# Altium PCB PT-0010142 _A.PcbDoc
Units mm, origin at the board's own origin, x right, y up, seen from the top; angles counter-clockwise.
Board outline 29.4 x 66.3 mm, 3 copper layers (Top Layer, MidLayer1, Bottom Layer), stack 1.608 mm thick; 32 components, 11 nets, 109 pads, 881 vias.
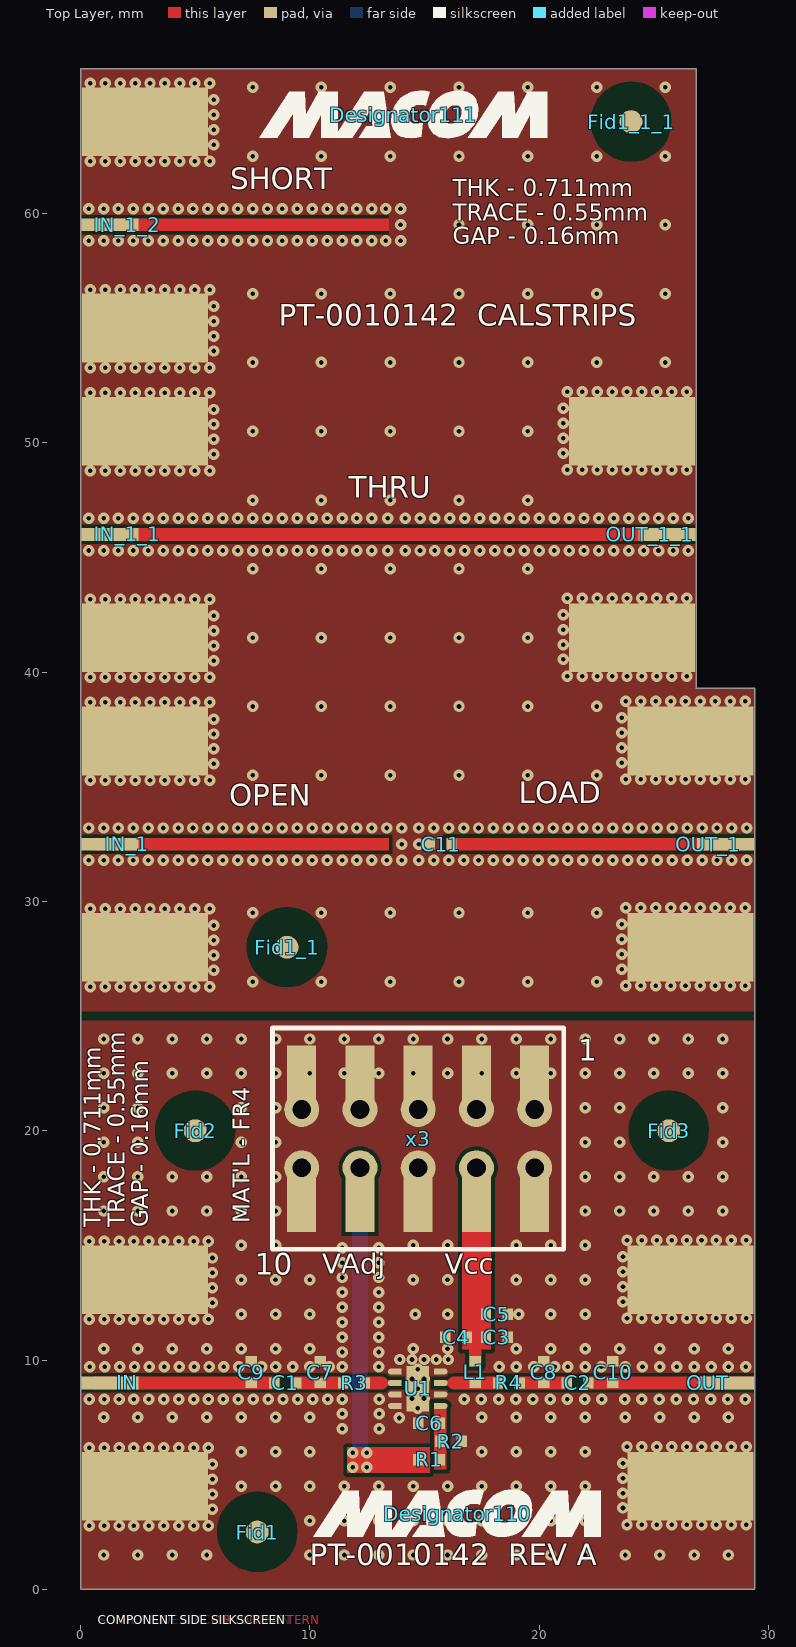
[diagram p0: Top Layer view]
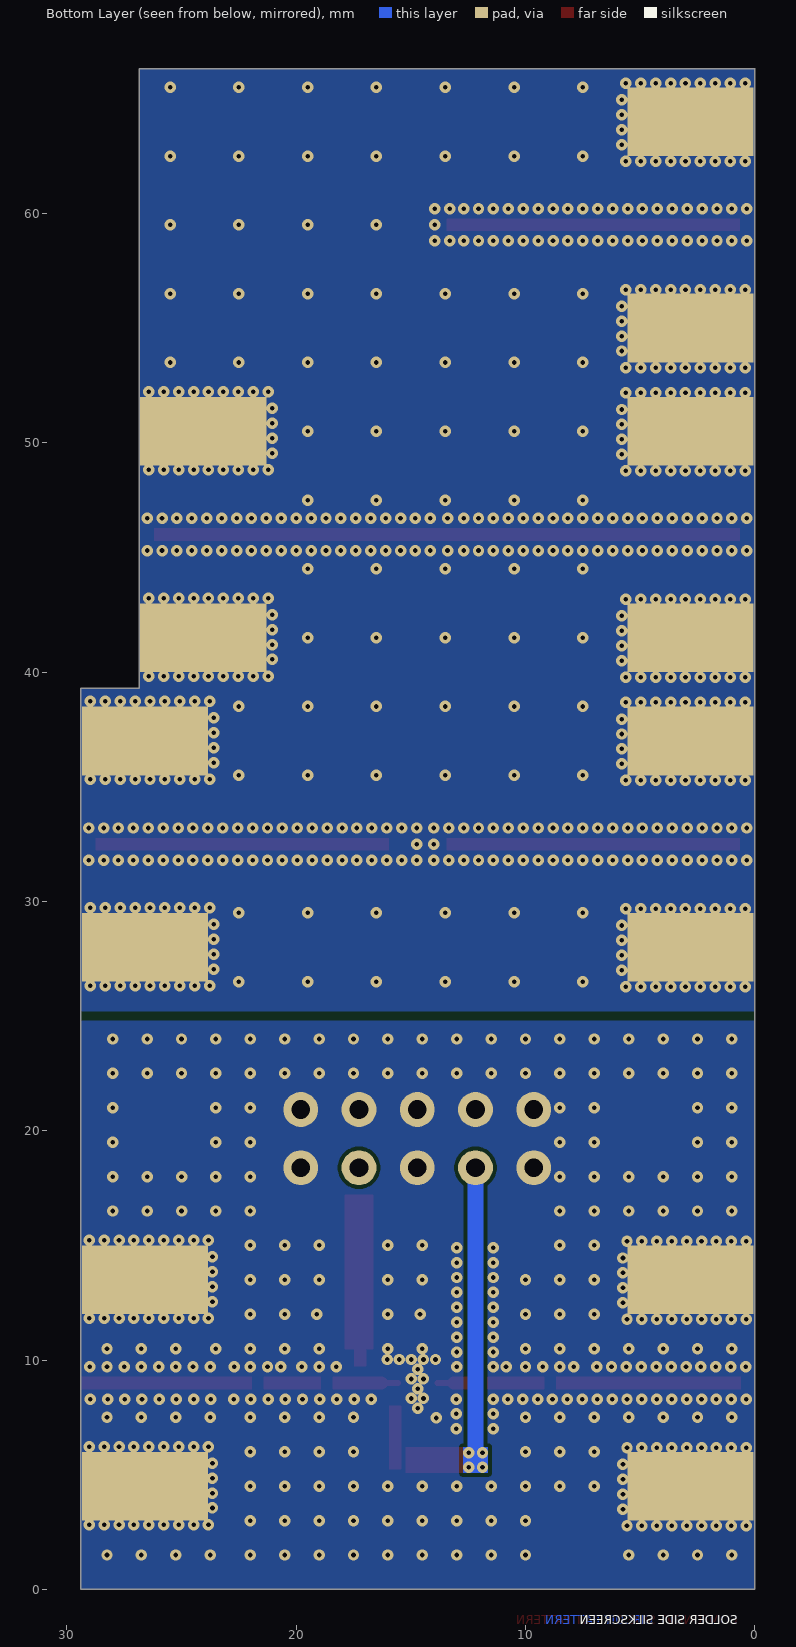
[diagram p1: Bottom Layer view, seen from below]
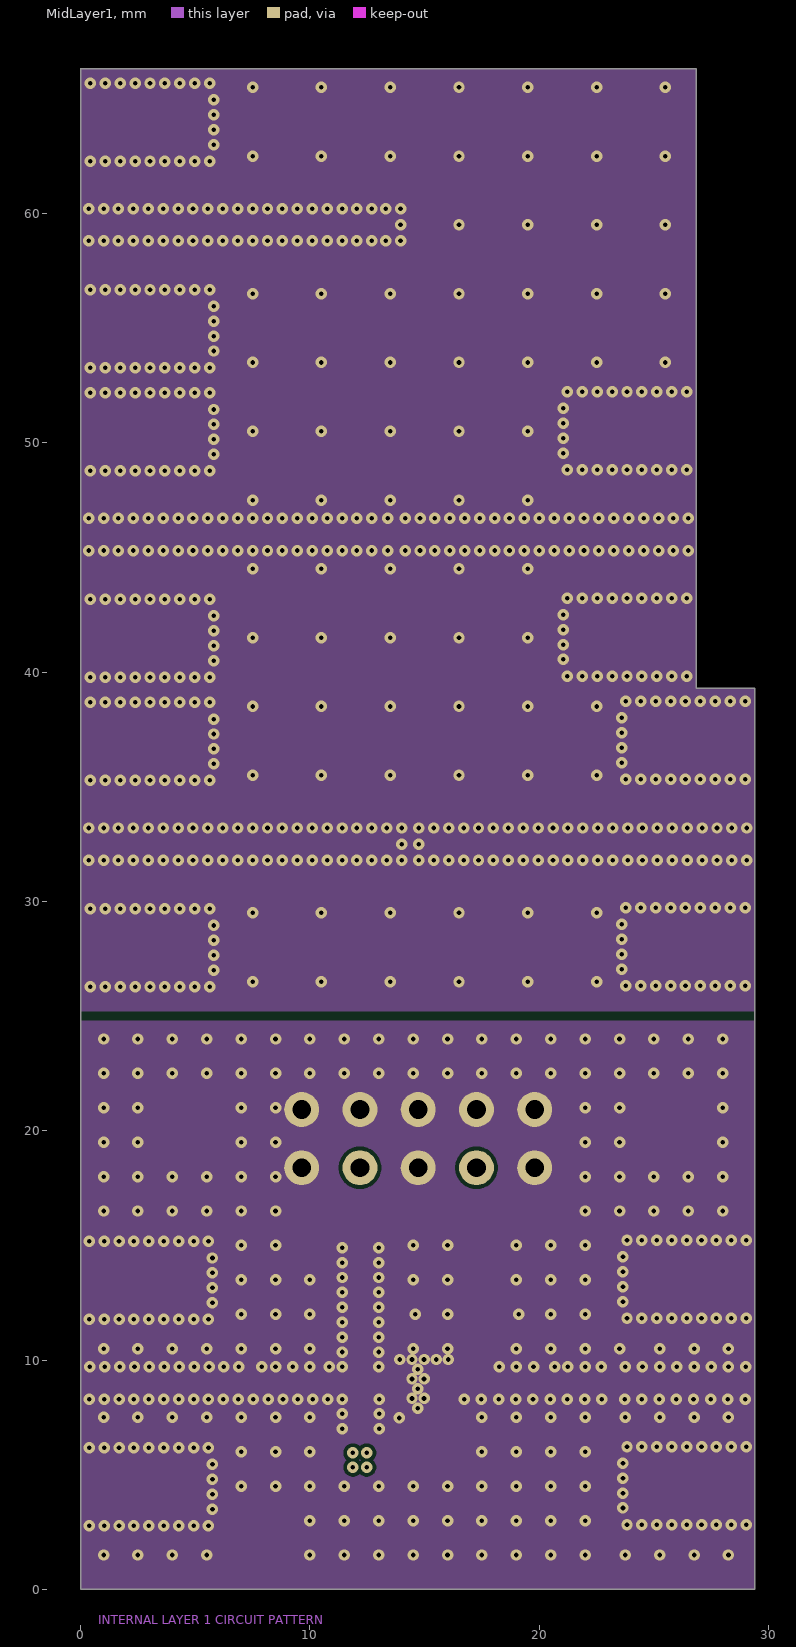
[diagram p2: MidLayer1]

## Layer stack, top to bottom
Top Solder: solder mask 0.0102, Solder Resist, Dk 3.5
Top Layer: signal copper 0.0356
Dielectric1: core 0.711, FR-4, Dk 4.8
MidLayer1: signal copper 0.0356
Dielectric2: prepreg 0.79, FR-4, Dk 4.8
Bottom Layer: signal copper 0.0356
Bottom Solder: solder mask 0.0102, Solder Resist, Dk 3.5

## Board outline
0,0 0,25 0,66.3 26.85,66.3 26.85,39.3 29.4,39.3 29.4,25 29.4,0

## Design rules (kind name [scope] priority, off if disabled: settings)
Clearance [All] p1: gap=0.16
ComponentClearance [All] p1: gap=0.15 collisioncheckmode=3 verticalgap=0.254 showdistances=FALSE
HoleSize [All] p1: absolutevalues=TRUE maxlimit=2.54 minlimit=0.02 maxpercent=80.000 minpercent=20.000
HoleToHoleClearance [All] p1: gap=0.15 allowstackedmicrovias=TRUE
MinimumSolderMaskSliver [All] p1: minsoldermaskwidth=0.149
PolygonConnect [All] p1: connectstyle=Direct reliefconductorwidth=0.254 reliefentries=4 polygonreliefangle="90 Angle" airgapwidth=0.254
RoomDefinition U_Individual [InComponentClass('U_Individual')] p1: confinementstyle=ConfineIn formatcopy=TRUE lockcomponents=FALSE outline -24.6,0 80.125,0 80.125,37 -24.6,37
RoomDefinition Sheet1 [InComponentClass('Sheet1')] p2: confinementstyle=ConfineIn formatcopy=TRUE lockcomponents=FALSE outline -24.875,-0.275 80.025,-0.275 80.025,37.2 -24.875,37.2
RoutingVias [All] p1: holewidth=0.25 width=0.5 viastyle="Through Hole" minholewidth=0.2 minwidth=0.6 maxholewidth=1 maxwidth=1.4
SilkToSilkClearance [All] p1: silktosilkclearance=0.2
SilkToSolderMaskClearance SilkscreenOverComponentPads [IsPad] p1: minsilkscreentomaskgap=0.1 clearancetoexposedcopper=TRUE
SolderMaskExpansion [All] p1: expansion=0.075
Width [All] p1: maxlimit=1.27 minlimit=0.2 preferedwidth=0.2
24 further rules are at their usual default settings.

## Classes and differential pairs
component class Sheet1: X3
component class U_Individual: R4

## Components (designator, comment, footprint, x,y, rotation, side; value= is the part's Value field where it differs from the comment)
C1 "#NAME?" 0402 8.925,9 r180 top
C2 "#NAME?" 0402 21.675,9 r180 top
C3 "#NAME?" 0402 18.15,11 r180 top
C4 "#NAME?" 0402 16.375,11 r180 top
C5 "#NAME?" 0402 18.15,12 r180 top
C6 "#NAME?" 0402 15.2,7.25 r0 top
C7 "#NAME?" 0402 10.45,9.475 r270 top
C8 "#NAME?" 0402 20.2,9.475 r270 top
C9 "#NAME?" 0402 7.45,9.475 r270 top
C10 "#NAME?" 0402 23.2,9.475 r270 top
C11 "#NAME?" 0402 15.7,32.5 r180 top (schematic designator C3)
Designator110 "Comment" LOGO-MACOM 16.425,3.3 r0 top
Designator111 "Comment" LOGO-MACOM 14.075,64.3 r0 top
Fid1 "Comment" Fiducial_1 7.7,2.5 r270 top
Fid1_1 "Comment" Fiducial_1 9,28 r270 top
Fid1_1_1 "Comment" Fiducial_1 24,64 r270 top
Fid2 "Comment" Fiducial_1 5,20 r270 top
Fid3 "Comment" Fiducial_1 25.65,20 r270 top
IN "Comment" "SMA_ Emerson_142-0701-851" 0,9 r0 top
IN_1 "Comment" "SMA_ Emerson_142-0701-851" 0,32.5 r0 top
IN_1_1 "Comment" "SMA_ Emerson_142-0701-851" 0,46 r0 top
IN_1_2 "Comment" "SMA_ Emerson_142-0701-851" 0,59.5 r0 top
L1 "#NAME?" 0402 17.2,9.475 r270 top
OUT "Comment" "SMA_ Emerson_142-0701-851" 29.4,9 r180 top
OUT_1 "Comment" "SMA_ Emerson_142-0701-851" 29.4,32.5 r180 top
OUT_1_1 "Comment" "SMA_ Emerson_142-0701-851" 26.85,46 r180 top
R1 "#NAME?" 0402 15.2,5.65 r0 top
R2 "#NAME?" 0402 16.15,6.45 r0 top
R3 "#NAME?" 0402 11.925,9 r180 top
R4 "#NAME?" 0402 18.675,9 r180 top
U1 "Comment" PDFN-8_2mm_Standard 14.7,8.75 r270 top
x3 "2X5_DUAL" 2X5_DUAL 19.8,20.925 r0 top locked (schematic designator X3)

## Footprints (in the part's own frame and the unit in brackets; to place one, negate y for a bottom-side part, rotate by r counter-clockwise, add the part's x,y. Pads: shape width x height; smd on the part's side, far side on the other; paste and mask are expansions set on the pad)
2X5_DUAL [mil]
  round 60 hole 32: 1(0,0) 2(0,-100) 3(-100,0) 4(-100,-100) 5(-200,0) 6(-200,-100) 7(-300,0) 8(-300,-100) 9(-400,0) 10(-400,-100)
  rect 50x110 smd: 1(0,55) 2(0,-155) 3(-100,55) 4(-100,-155) 5(-200,55) 6(-200,-155) 7(-300,55) 8(-300,-155) 9(-400,55) 10(-400,-155)
  silkscreen extent -450,-240 50,140, body extent -451,-150 49,50, height 205
0402 [mm]
  rect 0.45x0.5 smd mask+0.075: 1(-0.475,0) 2(0.475,0)
  body extent -0.5,-0.3 0.5,0.3, height 0.19
Fiducial_1 [mm] "Standard_1mm_Copper_3mm_Mask"
  round 1 smd paste-1 mask+1: 0(0,0)
  Top Layer pour cut-out: -1.75,-0.15 -1.725,-0.3 -1.675,-0.5 -1.6,-0.7 -1.507,-0.892 -1.35,-1.125 -1.175,-1.3 -1.025,-1.425 -0.875,-1.525 -0.65,-1.625 -0.35,-1.725 -0.125,-1.75 0.125,-1.75 0.45,-1.7 0.75,-1.575 1.05,-1.4 1.3,-1.175 1.45,-0.975 1.575,-0.775 1.65,-0.55 1.725,-0.275 1.75,0 1.725,0.275 1.674,0.532 1.55,0.8 1.425,1 1.25,1.225 1.025,1.425 0.725,1.6 0.5,1.675 0.25,1.725 -0.05,1.75 -0.325,1.725 -0.6,1.65 -0.875,1.525 -1.05,1.4 -1.225,1.25 -1.35,1.1 -1.5,0.9 -1.597,0.732 -1.675,0.525 -1.725,0.325 -1.75,0.15
LOGO-MACOM [mm]
  silkscreen extent -6.29,-1.01 6.27,1.05
PDFN-8_2mm_Standard [mm]
  oval 0.25x0.6 smd mask+0.05: 1(-0.75,-1) 2(-0.25,-1) 3(0.25,-1) 4(0.75,-1) 5(0.75,1) 6(0.25,1) 7(-0.25,1) 8(-0.75,1)
  rect 0.25x0.2 smd mask+0.05: 1(-0.75,-0.8) 2(-0.25,-0.8) 3(0.25,-0.8) 4(0.75,-0.8) 5(0.75,0.8) 6(0.25,0.8) 7(-0.25,0.8) 8(-0.75,0.8)
  rect 2x1 smd paste-0.1 mask-0.075: 9(0,0)
  body extent -1,-1 1,1, height 1
"SMA_ Emerson_142-0701-851" [mm]
  rect 2.5x0.55 smd mask+0.075: 1(1.275,0)
  rect 5.5x3 smd mask+0.075: 2(2.8,-4.5) 2(2.8,4.5)
  rect 5.5x3 smd far side mask+0.075: 2(2.8,-4.5) 2(2.8,4.5)
  body extent -9.08,-4.76 4.75,4.76, height 3.96

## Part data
C1 C2 C3 C4 C5 C6 C7 C8 C9 C10 C11 L1 R1 R2 R3 R4: library part C0402, "Capacitor"

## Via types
v1: diameter 0.5, hole 0.2, Top Layer to Bottom Layer, tented both sides, 881 vias

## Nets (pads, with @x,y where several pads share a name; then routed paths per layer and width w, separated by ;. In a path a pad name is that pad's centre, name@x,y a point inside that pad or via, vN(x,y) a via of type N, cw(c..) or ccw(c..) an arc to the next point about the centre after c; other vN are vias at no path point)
1: R3.1 U1.2 | length 1.4
  Top Layer w0.25: 13.125,9 13.7,9 U1.2@13.85,9
  Top Layer w0.55: R3.1@12.45,9 13.125,9
2: C1.1 C7.2 R3.2
3: C1.2 C9.2 IN.1
4: L1.2 R4.2 U1.7 | length 2.4
  Top Layer w0.25: U1.7@15.55,9 15.7,9 16.275,9
  Top Layer w0.55: 16.275,9 17.95,9
5: C2.2 C8.2 R4.1
6: C2.1 C10.2 OUT.1
7: C6.2 R1.2 R2.1 U1.5
GND: C3.1 C4.2 C5.1 C6.1 C7.1 C8.1 C9.1 C10.1 IN.2 OUT.2 R2.2 U1.1 U1.3 U1.4 U1.6 U1.8 U1.9 x3.1 x3.2 x3.3 x3.5 x3.6 x3.7 x3.9 x3.10
  other v1: 1,1.5 2.5,1.5 4,1.5 5.5,1.5 10,1.5 11.5,1.5 13,1.5 14.5,1.5 16,1.5 17.5,1.5 19,1.5 20.5,1.5 22,1.5 23.75,1.5 25.25,1.5 26.75,1.5 28.25,1.5 0.375,2.775 1.025,2.775 1.675,2.775 2.325,2.775 2.975,2.775 3.625,2.775 4.275,2.775 4.925,2.775 5.575,2.775 23.825,2.825 24.475,2.825 25.125,2.825 25.775,2.825 26.425,2.825 27.075,2.825 27.725,2.825 28.375,2.825 29.025,2.825 10,3 11.5,3 13,3 14.5,3 16,3 17.5,3 19,3 20.5,3 22,3 5.75,3.5 23.65,3.55 5.75,4.15 23.65,4.2 7,4.5 8.5,4.5 10,4.5 11.5,4.5 13,4.5 14.5,4.5 16,4.5 17.5,4.5 19,4.5 20.5,4.5 22,4.5 5.75,4.8 23.65,4.85 5.75,5.45 23.65,5.5 7,6 8.5,6 10,6 17.5,6 19,6 20.5,6 22,6 0.375,6.175 1.025,6.175 1.675,6.175 2.325,6.175 2.975,6.175 3.625,6.175 4.275,6.175 4.925,6.175 5.575,6.175 23.825,6.225 24.475,6.225 25.125,6.225 25.775,6.225 26.425,6.225 27.075,6.225 27.725,6.225 28.375,6.225 29.025,6.225 11.4,7 13.025,7 13.9,7.475 1,7.5 2.5,7.5 4,7.5 5.5,7.5 7,7.5 8.5,7.5 10,7.5 17.5,7.5 19,7.5 20.5,7.5 22,7.5 23.75,7.5 25.25,7.5 26.75,7.5 28.25,7.5 11.4,7.65 13.025,7.65 14.7,7.9 0.375,8.3 1.025,8.3 1.675,8.3 2.325,8.3 2.975,8.3 3.625,8.3 4.275,8.3 4.925,8.3 5.575,8.3 6.225,8.3 6.875,8.3 7.525,8.3 8.175,8.3 8.825,8.3 9.475,8.3 10.125,8.3 10.775,8.3 11.4,8.3 13.025,8.3 16.725,8.3 17.475,8.3 18.225,8.3 18.975,8.3 19.725,8.3 20.475,8.3 21.225,8.3 21.975,8.3 22.725,8.3 23.725,8.3 24.475,8.3 25.225,8.3 25.975,8.3 26.725,8.3 27.475,8.3 28.225,8.3 28.975,8.3 14.45,8.325 14.975,8.325 14.7,8.75 14.45,9.175 14.975,9.175 14.7,9.6 0.4,9.7 1.05,9.7 1.7,9.7 2.35,9.7 3,9.7 3.65,9.7 4.3,9.7 4.95,9.7 5.6,9.7 6.25,9.7 6.9,9.7 7.9,9.7 8.5,9.7 9.25,9.7 10,9.7 10.85,9.7 11.4,9.7 13,9.7 18.25,9.7 19,9.7 19.75,9.7 20.675,9.7 21.25,9.7 22,9.7 22.7,9.7 23.75,9.7 24.5,9.7 25.25,9.7 26,9.7 26.75,9.7 27.5,9.7 28.25,9.7 29,9.7 13.925,10.025 14.45,10.025 14.975,10.025 15.5,10.025 16.025,10.025 11.4,10.35 13,10.35 1,10.5 2.5,10.5 4,10.5 5.5,10.5 7,10.5 8.5,10.5 10,10.5 14.5,10.5 16,10.5 19,10.5 20.5,10.5 22,10.5 23.5,10.5 25.25,10.5 26.75,10.5 28.25,10.5 11.4,11 13,11 11.4,11.65 13,11.65 0.375,11.775 1.025,11.775 1.675,11.775 2.325,11.775 2.975,11.775 3.625,11.775 4.275,11.775 4.925,11.775 5.575,11.775 23.825,11.825 24.475,11.825 25.125,11.825 25.775,11.825 26.425,11.825 27.075,11.825 27.725,11.825 28.375,11.825 29.025,11.825 7,12 8.5,12 10,12 14.6,12 16,12 19.1,12 20.5,12 22,12 11.4,12.3 13,12.3 5.75,12.5 23.65,12.55 11.4,12.95 13,12.95 5.75,13.15 23.65,13.2 7,13.5 8.5,13.5 10,13.5 14.5,13.5 16,13.5 19,13.5 20.5,13.5 22,13.5 11.4,13.6 13,13.6 5.75,13.8 23.65,13.85 11.4,14.25 13,14.25 5.75,14.45 23.65,14.5 11.4,14.9 13,14.9 7,15 8.5,15 14.5,15 16,15 19,15 20.5,15 22,15 0.375,15.175 1.025,15.175 1.675,15.175 2.325,15.175 2.975,15.175 3.625,15.175 4.275,15.175 4.925,15.175 5.575,15.175 23.825,15.225 24.475,15.225 25.125,15.225 25.775,15.225 26.425,15.225 27.075,15.225 27.725,15.225 28.375,15.225 29.025,15.225 1,16.5 2.5,16.5 4,16.5 5.5,16.5 7,16.5 8.5,16.5 22,16.5 23.5,16.5 25,16.5 26.5,16.5 28,16.5 1,18 2.5,18 4,18 5.5,18 7,18 8.5,18 22,18 23.5,18 25,18 26.5,18 28,18 1,19.5 2.5,19.5 7,19.5 8.5,19.5 22,19.5 23.5,19.5 28,19.5 1,21 2.5,21 7,21 8.5,21 22,21 23.5,21 28,21 1,22.5 2.5,22.5 4,22.5 5.5,22.5 7,22.5 8.5,22.5 10,22.5 11.5,22.5 13,22.5 14.5,22.5 16,22.5 17.5,22.5 19,22.5 20.5,22.5 22,22.5 23.5,22.5 25,22.5 26.5,22.5 28,22.5 1,24 2.5,24 4,24 5.5,24 7,24 8.5,24 10,24 11.5,24 13,24 14.5,24 16,24 17.5,24 19,24 20.5,24 22,24 23.5,24 25,24 26.5,24 28,24
GND2: C11.2 IN_1.2 IN_1_1.2 IN_1_2.1 IN_1_2.2 OUT_1.2 OUT_1_1.2
  other v1: 0.425,26.275 1.075,26.275 1.725,26.275 2.375,26.275 3.025,26.275 3.675,26.275 4.325,26.275 4.975,26.275 5.625,26.275 23.775,26.325 24.425,26.325 25.075,26.325 25.725,26.325 26.375,26.325 27.025,26.325 27.675,26.325 28.325,26.325 28.975,26.325 7.5,26.5 10.5,26.5 13.5,26.5 16.5,26.5 19.5,26.5 22.5,26.5 5.8,27 23.6,27.05 5.8,27.65 23.6,27.7 5.8,28.3 23.6,28.35 5.8,28.95 23.6,29 7.5,29.5 10.5,29.5 13.5,29.5 16.5,29.5 19.5,29.5 22.5,29.5 0.425,29.675 1.075,29.675 1.725,29.675 2.375,29.675 3.025,29.675 3.675,29.675 4.325,29.675 4.975,29.675 5.625,29.675 23.775,29.725 24.425,29.725 25.075,29.725 25.725,29.725 26.375,29.725 27.025,29.725 27.675,29.725 28.325,29.725 28.975,29.725 0.35,31.8 1,31.8 1.65,31.8 2.3,31.8 2.95,31.8 3.6,31.8 4.25,31.8 4.9,31.8 5.55,31.8 6.2,31.8 6.85,31.8 7.5,31.8 8.15,31.8 8.8,31.8 9.45,31.8 10.1,31.8 10.75,31.8 11.4,31.8 12.05,31.8 12.7,31.8 13.35,31.8 14,31.8 14.75,31.8 15.4,31.8 16.05,31.8 16.7,31.8 17.35,31.8 18,31.8 18.65,31.8 19.3,31.8 19.95,31.8 20.6,31.8 21.25,31.8 21.9,31.8 22.55,31.8 23.2,31.8 23.85,31.8 24.5,31.8 25.15,31.8 25.8,31.8 26.45,31.8 27.1,31.8 27.75,31.8 28.4,31.8 29.05,31.8 14,32.5 14.75,32.5 0.35,33.2 1,33.2 1.65,33.2 2.3,33.2 2.95,33.2 3.6,33.2 4.25,33.2 4.9,33.2 5.55,33.2 6.2,33.2 6.85,33.2 7.5,33.2 8.15,33.2 8.8,33.2 9.45,33.2 10.1,33.2 10.75,33.2 11.4,33.2 12.05,33.2 12.7,33.2 13.35,33.2 14,33.2 14.75,33.2 15.4,33.2 16.05,33.2 16.7,33.2 17.35,33.2 18,33.2 18.65,33.2 19.3,33.2 19.95,33.2 20.6,33.2 21.25,33.2 21.9,33.2 22.55,33.2 23.2,33.2 23.85,33.2 24.5,33.2 25.15,33.2 25.8,33.2 26.45,33.2 27.1,33.2 27.75,33.2 28.4,33.2 29.05,33.2 0.425,35.275 1.075,35.275 1.725,35.275 2.375,35.275 3.025,35.275 3.675,35.275 4.325,35.275 4.975,35.275 5.625,35.275 23.775,35.325 24.425,35.325 25.075,35.325 25.725,35.325 26.375,35.325 27.025,35.325 27.675,35.325 28.325,35.325 28.975,35.325 7.5,35.5 10.5,35.5 13.5,35.5 16.5,35.5 19.5,35.5 22.5,35.5 5.8,36 23.6,36.05 5.8,36.65 23.6,36.7 5.8,37.3 23.6,37.35 5.8,37.95 23.6,38 7.5,38.5 10.5,38.5 13.5,38.5 16.5,38.5 19.5,38.5 22.5,38.5 0.425,38.675 1.075,38.675 1.725,38.675 2.375,38.675 3.025,38.675 3.675,38.675 4.325,38.675 4.975,38.675 5.625,38.675 23.775,38.725 24.425,38.725 25.075,38.725 25.725,38.725 26.375,38.725 27.025,38.725 27.675,38.725 28.325,38.725 28.975,38.725 0.425,39.775 1.075,39.775 1.725,39.775 2.375,39.775 3.025,39.775 3.675,39.775 4.325,39.775 4.975,39.775 5.625,39.775 21.225,39.825 21.875,39.825 22.525,39.825 23.175,39.825 23.825,39.825 24.475,39.825 25.125,39.825 25.775,39.825 26.425,39.825 5.8,40.5 21.05,40.55 5.8,41.15 21.05,41.2 7.5,41.5 10.5,41.5 13.5,41.5 16.5,41.5 19.5,41.5 5.8,41.8 21.05,41.85 5.8,42.45 21.05,42.5 0.425,43.175 1.075,43.175 1.725,43.175 2.375,43.175 3.025,43.175 3.675,43.175 4.325,43.175 4.975,43.175 5.625,43.175 21.225,43.225 21.875,43.225 22.525,43.225 23.175,43.225 23.825,43.225 24.475,43.225 25.125,43.225 25.775,43.225 26.425,43.225 7.5,44.5 10.5,44.5 13.5,44.5 16.5,44.5 19.5,44.5 0.35,45.3 1,45.3 1.65,45.3 2.3,45.3 2.95,45.3 3.6,45.3 4.25,45.3 4.9,45.3 5.55,45.3 6.2,45.3 6.85,45.3 7.5,45.3 8.15,45.3 8.8,45.3 9.45,45.3 10.1,45.3 10.75,45.3 11.4,45.3 12.05,45.3 12.7,45.3 13.4,45.3 14.15,45.3 14.8,45.3 15.45,45.3 16.1,45.3 16.75,45.3 17.4,45.3 18.05,45.3 18.7,45.3 19.35,45.3 20,45.3 20.65,45.3 21.3,45.3 21.95,45.3 22.6,45.3 23.25,45.3 23.9,45.3 24.55,45.3 25.2,45.3 25.85,45.3 26.5,45.3 0.35,46.7 1,46.7 1.65,46.7 2.3,46.7 2.95,46.7 3.6,46.7 4.25,46.7 4.9,46.7 5.55,46.7 6.2,46.7 6.85,46.7 7.5,46.7 8.15,46.7 8.8,46.7 9.45,46.7 10.1,46.7 10.75,46.7 11.4,46.7 12.05,46.7 12.7,46.7 13.4,46.7 14.15,46.7 14.8,46.7 15.45,46.7 16.1,46.7 16.75,46.7 17.4,46.7 18.05,46.7 18.7,46.7 19.35,46.7 20,46.7 20.65,46.7 21.3,46.7 21.95,46.7 22.6,46.7 23.25,46.7 23.9,46.7 24.55,46.7 25.2,46.7 25.85,46.7 26.5,46.7 7.5,47.5 10.5,47.5 13.5,47.5 16.5,47.5 19.5,47.5 0.425,48.775 1.075,48.775 1.725,48.775 2.375,48.775 3.025,48.775 3.675,48.775 4.325,48.775 4.975,48.775 5.625,48.775 21.225,48.825 21.875,48.825 22.525,48.825 23.175,48.825 23.825,48.825 24.475,48.825 25.125,48.825 25.775,48.825 26.425,48.825 5.8,49.5 21.05,49.55 5.8,50.15 21.05,50.2 7.5,50.5 10.5,50.5 13.5,50.5 16.5,50.5 19.5,50.5 5.8,50.8 21.05,50.85 5.8,51.45 21.05,51.5 0.425,52.175 1.075,52.175 1.725,52.175 2.375,52.175 3.025,52.175 3.675,52.175 4.325,52.175 4.975,52.175 5.625,52.175 21.225,52.225 21.875,52.225 22.525,52.225 23.175,52.225 23.825,52.225 24.475,52.225 25.125,52.225 25.775,52.225 26.425,52.225 0.425,53.275 1.075,53.275 1.725,53.275 2.375,53.275 3.025,53.275 3.675,53.275 4.325,53.275 4.975,53.275 5.625,53.275 7.5,53.5 10.5,53.5 13.5,53.5 16.5,53.5 19.5,53.5 22.5,53.5 25.5,53.5 5.8,54 5.8,54.65 5.8,55.3 5.8,55.95 7.5,56.5 10.5,56.5 13.5,56.5 16.5,56.5 19.5,56.5 22.5,56.5 25.5,56.5 0.425,56.675 1.075,56.675 1.725,56.675 2.375,56.675 3.025,56.675 3.675,56.675 4.325,56.675 4.975,56.675 5.625,56.675 0.35,58.8 1,58.8 1.65,58.8 2.3,58.8 2.95,58.8 3.6,58.8 4.25,58.8 4.9,58.8 5.55,58.8 6.2,58.8 6.85,58.8 7.5,58.8 8.15,58.8 8.8,58.8 9.45,58.8 10.1,58.8 10.75,58.8 11.4,58.8 12.05,58.8 12.7,58.8 13.3,58.8 13.95,58.8 13.95,59.5 16.5,59.5 19.5,59.5 22.5,59.5 25.5,59.5 0.35,60.2 1,60.2 1.65,60.2 2.3,60.2 2.95,60.2 3.6,60.2 4.25,60.2 4.9,60.2 5.55,60.2 6.2,60.2 6.85,60.2 7.5,60.2 8.15,60.2 8.8,60.2 9.45,60.2 10.1,60.2 10.75,60.2 11.4,60.2 12.05,60.2 12.7,60.2 13.3,60.2 13.95,60.2 0.425,62.275 1.075,62.275 1.725,62.275 2.375,62.275 3.025,62.275 3.675,62.275 4.325,62.275 4.975,62.275 5.625,62.275 7.5,62.5 10.5,62.5 13.5,62.5 16.5,62.5 19.5,62.5 22.5,62.5 25.5,62.5 5.8,63 5.8,63.65 5.8,64.3 5.8,64.95 7.5,65.5 10.5,65.5 13.5,65.5 16.5,65.5 19.5,65.5 22.5,65.5 25.5,65.5 0.425,65.675 1.075,65.675 1.725,65.675 2.375,65.675 3.025,65.675 3.675,65.675 4.325,65.675 4.975,65.675 5.625,65.675
VAdj: R1.1 x3.8
  other v1: 11.875,5.325 12.475,5.325 11.875,5.95 12.475,5.95
VCC: C3.2 C4.1 C5.2 L1.1 x3.4
pads on no net: C11.1 Fid1.0 Fid1_1.0 Fid1_1_1.0 Fid2.0 Fid3.0 IN_1.1 IN_1_1.1 OUT_1.1 OUT_1_1.1

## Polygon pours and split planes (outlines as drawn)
GND2 on Top Layer "gnd" (solid, pour order 39): 0,25.2 29.4,25.2 29.4,39.3 26.85,39.3 26.85,66.3 0,66.3
GND on Top Layer "gnd" (solid, pour order 47): 0,0 29.4,0 29.4,24.8 0,24.8
GND on MidLayer1 "gnd" (solid, pour order 23): 0,0 29.4,0 29.4,24.8 0,24.8
GND2 on MidLayer1 "gnd" (solid, pour order 49): 0,25.2 29.4,25.2 29.4,39.3 26.85,39.3 26.85,66.3 0,66.3
GND on Bottom Layer "gnd" (solid, pour order 26): 0,0 29.4,0 29.4,24.8 0,24.8
GND2 on Bottom Layer "gnd" (solid, pour order 51): 0,25.2 29.4,25.2 29.4,39.3 26.85,39.3 26.85,66.3 0,66.3

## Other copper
Top Layer:
  region net VAdj: 15.239,5.075 15.239,6.2 11.625,6.2 11.625,5.075
  region net 7: 15.4,8.025 15.4,5.225 15.95,5.225 15.95,8.025
  region net VCC: 17.9,10.45 17.9,17.213 16.625,17.213 16.625,10.45
  rectangle net 4: 17.625,8.725 18.425,9.275
  region net 1: 12.975,9.275 12.175,9.275 12.175,8.725 12.975,8.725
  region net VCC: 16.925,12.8 16.925,9.725 17.475,9.725 17.475,12.8
  region net 6: 29.4,9.275 21.925,9.275 21.925,8.725 29.4,8.725
  rectangle net 5: 18.925,8.725 21.425,9.275
  rectangle net 3: 0.6,8.725 8.675,9.275
  rectangle net 2: 9.175,8.725 11.675,9.275
  rectangle: 0.65,32.225 13.45,32.775
  region: 28.75,32.775 15.95,32.775 15.95,32.225 28.75,32.225
  region: 26.2,46.275 13.4,46.275 13.4,45.725 26.2,45.725
  rectangle: 0.65,45.725 13.45,46.275
  rectangle net GND2: 0.65,59.225 13.45,59.775
  pour cut-out: 0,8.565 0,9.435 13.4,9.435 13.4,8.565
  pour cut-out: 29.4,9.435 29.4,8.565 16,8.565 16,9.435
  pour cut-out: 29.35,32.935 29.35,32.065 15.95,32.065 15.95,32.935
  pour cut-out: 0.05,32.065 0.05,32.935 13.61,32.935 13.61,32.065
  pour cut-out: 29.35,32.935 29.35,32.065 15.79,32.065 15.79,32.935
  pour cut-out: 26.8,46.435 26.8,45.565 13.24,45.565 13.24,46.435
  pour cut-out: 0,45.565 0,46.435 13.56,46.435 13.56,45.565
  pour cut-out: 26.8,46.435 26.8,45.565 13.4,45.565 13.4,46.435
  pour cut-out: 0,59.065 0,59.935 13.45,59.935 13.45,59.065
  text "COMPONENT SIDE CIRCUIT PATTERN" at 0.75,-1.65 h0.65
MidLayer1:
  text "INTERNAL LAYER 1 CIRCUIT PATTERN" at 0.775,-1.653 h0.65
Bottom Layer:
  region net VAdj: 12.725,5.075 12.725,6.2 11.625,6.2 11.625,5.075
  region net VAdj: 12.525,5.075 12.525,18.385 11.825,18.385 11.825,5.075
  text "SOLDER SIDE CIRCUIT PATTERN" at 0.775,-1.653 h0.65

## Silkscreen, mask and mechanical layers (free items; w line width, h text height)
Top Overlay:
  text "SHORT" at 6.525,60.75 h1.6
  text "THK - 0.711mm" at 16.225,60.5 h1.25
  text "TRACE - 0.55mm" at 16.225,59.45 h1.25
  text "GAP - 0.16mm" at 16.225,58.425 h1.25
  text "PT-0010142  CALSTRIPS" at 8.65,54.8 h1.6
  text "THRU" at 11.7,47.3 h1.6
  text "LOAD" at 19.1,33.975 h1.6
  text "OPEN" at 6.475,33.875 h1.6
  text "MAT'L - FR4" at 7.625,15.975 h1.25 r90
  text "THK - 0.711mm" at 1.125,15.8 h1.25 r90
  text "TRACE - 0.55mm" at 2.175,15.8 h1.25 r90
  text "GAP - 0.16mm" at 3.2,15.8 h1.25 r90
  text "VAdj" at 10.545,13.45 h1.5
  text "Vcc" at 15.875,13.45 h1.5
  text "PT-0010142  REV A" at 10,0.75 h1.6
  text "COMPONENT SIDE SILKSCREEN" at 0.75,-1.653 h0.65
Bottom Overlay:
  text "SOLDER SIDE SILKSCREEN" at 0.75,-1.653 h0.65
Top Paste:
  text "COMPONENT SIDE SOLDER PASTE" at 0.75,-1.653 h0.65
Bottom Paste:
  text "SOLDER SIDE SOLDER PASTE DEPOSITION TEMPLATE" at 0.75,-1.653 h0.65
Top Solder:
  text "COMPONENT SIDE SOLDERMASK" at 0.75,-1.653 h0.65
Bottom Solder:
  text "SOLDER SIDE SOLDERMASK" at 0.75,-1.653 h0.65
Mechanical 1:
  lines w0.001: 0,25 0,0 29.4,0 29.4,25 ; 0,25 29.4,25 ; 0,25 0,66.3 26.85,66.3 26.85,39.3 29.4,39.3 29.4,25
  text "THK - 0.711mm" at 16.225,60.5 h1.25
  text "TRACE - 0.55mm" at 16.225,59.45 h1.25
  text "GAP - 0.16mm" at 16.225,58.425 h1.25
  text "MAT'L - FR4" at 7.625,15.975 h1.25 r90
  text "THK - 0.711mm" at 1.125,15.8 h1.25 r90
  text "TRACE - 0.55mm" at 2.175,15.8 h1.25 r90
  text "GAP - 0.16mm" at 3.2,15.8 h1.25 r90
  text "PT-0010142  REV A" at 10,0.75 h1.6
  text "COMPONENT SIDE ASSEMBLY DRAWING" at 0.738,-1.662 h0.65
Mechanical 2:
  lines w0.001: 0,0 0,25 29.4,25 29.4,0 0,0
  text "SOLDER SIDE ASSEMBLY DRAWING" at 0.775,-1.653 h0.65
Mechanical 4 (All Layers):
  text "ALL ARTWORKS VIEWED FROM THE COMPONENT SIDE." at 0.775,-0.978 h0.65
  text "25-APRIL-15    PT-0010142   REVISION A" at 0.775,-2.328 h0.65
Drill Drawing:
  circle w0.254: c32.639,27.801 r0.345
  region: 41.434,67.595 41.434,38.095 41.934,38.095 41.934,67.595
  region: 44.434,67.595 44.434,38.095 44.934,38.095 44.934,67.595
  region: 48.433,67.595 48.433,38.095 48.934,38.095 48.934,67.595
  lines w0.001: -4.25,25 -0.5,25 ; -4.25,66.3 -0.5,66.3 ; -3.75,-0.001 -0.25,-0.001 ; 0,-3.751 0,-0.251 ; 26.85,66.8 26.85,69.8 ; 29.4,39.8 29.4,42.8 ; 38.434,77.595 41.434,77.595 ; 38.934,70.595 41.934,70.595 ; 39.433,35.595 41.434,37.595 ; 39.934,77.095 41.434,77.595 ; 39.934,78.095 41.434,77.595 ; 40.434,70.095 41.934,70.595 ; 40.434,71.095 41.934,70.595 ; 41.434,68.095 41.434,70.095 ; 41.434,71.095 41.434,78.595 ; 41.934,39.095 48.433,39.095 ; 41.934,66.595 48.433,66.595 ; 41.934,68.095 41.934,71.595 ; 44.434,68.095 44.434,71.595 ; 44.934,37.595 46.434,36.095 48.433,36.095 50.434,34.095 ; 45.934,70.095 44.434,70.595 ; 45.934,71.095 44.434,70.595 ; 47.934,70.595 44.434,70.595 ; 48.934,37.595 50.434,36.095 ; 48.934,68.095 48.934,78.595 ; 50.434,77.095 48.934,77.595 ; 50.434,78.095 48.934,77.595 ; 52.434,77.595 48.934,77.595 ; 0,25 0,66.3 26.85,66.3 26.85,39.3 29.4,39.3 29.4,25 ; 0,25 29.4,25 ; 0,25 0,0 29.4,0 29.4,25
  lines w0.025: 31.629,25.44 55.455,25.44 ; 31.629,28.543 55.455,28.543 ; 35.62,23.888 35.62,30.094 ; 39.837,23.888 39.837,30.094 ; 47.389,23.888 47.389,30.094 ; 50.483,23.888 50.483,30.094 ; 31.629,23.888 55.455,23.888 55.455,30.094 31.629,30.094 31.629,23.888
  lines w0.254: 32.294,25.905 32.639,26.077 32.984,25.905 32.812,26.25 32.984,26.595 32.639,26.422 32.294,26.595 32.467,26.25 32.294,25.905
  text "1.6mm" at 43.016,76.526 h1.8
  text "0.711mm" at 32.011,69.526 h1.8
  text "26.85 mm" at 26.725,66.95 h0.65 r90
  text "66.30 mm" at -4.201,66.4 h0.65
  text "29.40 mm" at 29.275,39.95 h0.65 r90
  text "Comp" at 35.127,34.526 h1.8
  text "Sold" at 50.933,34.526 h1.8
  text "Int1" at 50.933,32.526 h1.8
  text "Symbol" at 32.56,29.008 h0.9
  text "Hit Count" at 36.085,29.008 h0.9
  text "Finished Hole Size" at 40.303,29.008 h0.9
  text "Plated" at 47.854,29.008 h0.9
  text "Hole Type" at 50.949,29.008 h0.9
  text "10" at 36.085,27.457 h0.75
  text "0.813mm" at 40.303,27.457 h0.75
  text "PTH" at 47.854,27.457 h0.75
  text "Round" at 50.949,27.457 h0.75
  text "881" at 36.085,25.905 h0.75
  text "0.200mm" at 40.303,25.905 h0.75
  text "PTH" at 47.854,25.905 h0.75
  text "Round" at 50.949,25.905 h0.75
  text "25.00 mm" at -4.201,25.1 h0.65
  text "SCORELINE" at -4.201,24.5 h0.65
  text "891 Total" at 36.085,24.353 h0.75
  text "NOTES:" at 32.265,22.045 h0.75
  text "1.   Material:   FR4 per IPC4101/99, Double sided, Finished PCB Thickness 1.6mm +/- 10%" at 32.265,21.045 h0.75
  text "Dielectric Constant to be no greater than 4.6." at 32.265,20.045 h0.75
  text "Copper both sides  - Finished Thickness 0.044mm +/- 0.010mm." at 32.265,19.045 h0.75
  text "Finish: ENIG - 0.05-0.15uM Gold over 3 - 6uM Nickel over Copper." at 32.265,18.045 h0.75
  text "2.   Solder Resist: Green, Soldermask over bare copper. Location Tolerance +/-50 microns." at 32.265,17.045 h0.75
  text "3.   Excellon Drill Data originper X-Y Datum as Shown" at 32.265,16.045 h0.75
  text "4.   Tolerance: +/-0.050 mm on all track dimensions." at 32.265,15.045 h0.75
  text "Finished Hole Size tolerances to be +/-0.1mm." at 32.265,14.045 h0.75
  text "Board Outline tolerances to be +/-0.1mm." at 32.265,13.045 h0.75
  text "Soldermask Location Tolerance +/-50 microns." at 37.715,12.12 h0.75
  text "All other dimensional tolerances to be +/-0.1mm." at 32.265,11.045 h0.75
  text "5.   Manufacture per IPC-6012 (Latest Revision). PCB must meet acceptability" at 32.265,10.045 h0.75
  text "criteria as defined by IPC-A-600 (Latest Revision) Class II, and the" at 32.265,9.045 h0.75
  text "criteria defined in MACom Technology Solutions Quality Procedure QP-249." at 32.265,8.045 h0.75
  text "Both surfaces to be free from pits, bumps, and scratches. Remove all burrs" at 32.265,7.045 h0.75
  text "caused by routing. Take care not to damage copper plating during routing." at 32.265,6.045 h0.75
  text "Copper close to board edge - Exposure is acceptable." at 32.265,5.045 h0.75
  text "6.  All pcbs to be cleaned prior to dispatch. Ship all boards in sealed vacuum" at 32.277,4.085 h0.75
  text "packaging. Protect from damage during shipment." at 32.277,3.085 h0.75
  text "7.  Supplier will state on the Certificate of Conformance if any of the following" at 32.277,2.085 h0.75
  text "banned substances are used in the PCB or in the fabrication process:" at 32.277,1.085 h0.75
  text "Y-Datum" at -3.75,0.099 h0.65
  text "Polybrominated Biphenylethers, Polybrominated Biphenyls, Cadmium," at 32.277,0.085 h0.75
  text "Mercury, Chromium V1, or Beryllium." at 32.277,-0.915 h0.75
  text "DRILL DRAWING AND MECHANICAL INFORMATION" at 0.775,-1.653 h0.65
  text "8.  Certificate of Conformance addressing notes 1, 4, 5 and 7 may be requested." at 32.277,-1.915 h0.75
  text "X-Datum" at -0.099,-3.75 h0.65 r90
